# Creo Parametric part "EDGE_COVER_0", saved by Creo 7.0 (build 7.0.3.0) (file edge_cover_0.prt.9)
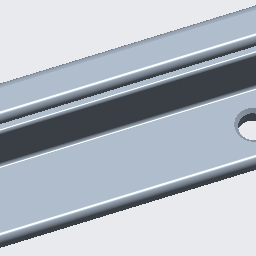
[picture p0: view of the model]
Units: millimeter Kilogram Sec (mmKs); MM, KILOGRAM, SECS

Created from: XX_SOLID_PART_MMKS_ABS.PRT

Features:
  1. coordinate system
  2. datum plane "RIGHT"
  3. datum plane "TOP"
  4. datum plane "FRONT"
  5. extrusion "Extrude 1"
  6. extruded cut "Extrude 2"
  7. round "Round 1"
  8. round "Round 2"
  9. round "Round 3"
  10. chamfer "Chamfer 1"

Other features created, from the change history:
  round "Round 1"
  round "Round 2"
  round "Round 3"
